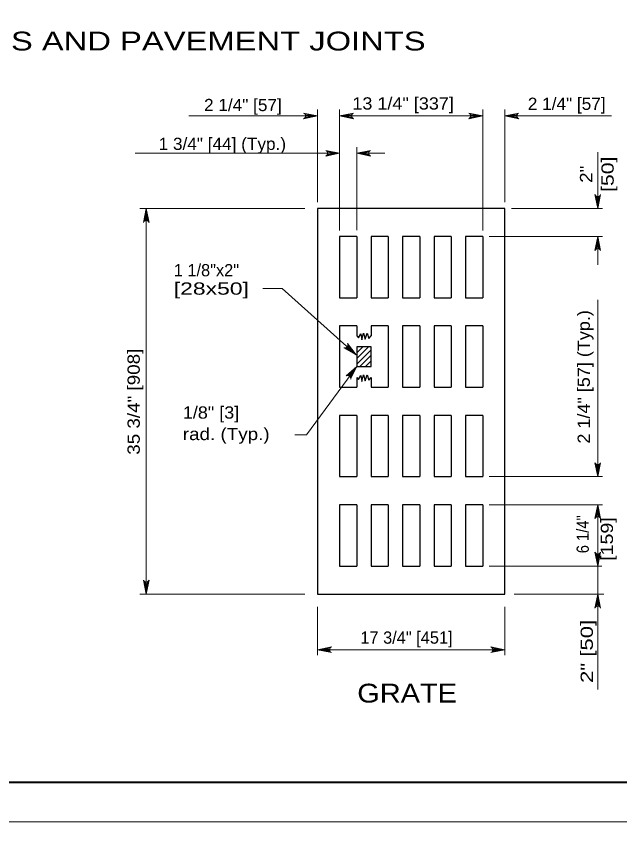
# Model space of a CAD drawing. Extents: x 1083.1 to 1117.1, y 719.4 to 763.4.
# Drawn here: x 1095.88 to 1103.56, y 741.1 to 751.62 of the extents above; entities that cross this region are included whole.
import ezdxf
from ezdxf.enums import TextEntityAlignment as Align

# ---------------------------------------------------------------- set-up
doc = ezdxf.new("R2010")
doc.units = 0
doc.header["$LTSCALE"] = 0.062
doc.linetypes.add('LONG_DASHED', pattern=[7.5, 6, -1.5])
doc.layers.add('1', color=7, linetype='Continuous', lineweight=13)

msp = doc.modelspace()

# ---------------------------------------------------------------- linework, layer by layer
at = {"layer": '1'}
for p, q in [((1099.55183, 750.37458), (1099.71208, 750.35217)), ((1099.55725, 750.3635), (1099.71208, 750.35217)), ((1099.99325, 748.89175), (1099.99325, 750.43542)), ((1100.15358, 750.37458), (1099.99325, 750.35217)), ((1100.14817, 750.3635), (1099.99325, 750.35217)), ((1101.65758, 750.37458), (1101.81792, 750.35217)), ((1101.66308, 750.3635), (1101.81792, 750.35217)), ((1101.81792, 748.89175), (1101.81792, 750.43542)), ((1102.09908, 749.25492), (1102.09908, 750.43542)), ((1102.25942, 750.37458), (1102.09908, 750.35217)), ((1102.254, 750.3635), (1102.09908, 750.35217)), ((1099.71208, 750.35217), (1098.07217, 750.35217)), ((1099.4615, 750.35217), (1099.71208, 750.35217)), ((1099.54992, 750.32733), (1099.71208, 750.35217)), ((1099.55608, 750.33775), (1099.71208, 750.35217)), ((1099.55892, 750.35217), (1099.71208, 750.35217)), ((1100.1465, 750.35217), (1099.99325, 750.35217)), ((1100.14933, 750.33775), (1099.99325, 750.35217)), ((1100.1555, 750.32733), (1099.99325, 750.35217)), ((1101.81792, 750.35217), (1099.99325, 750.35217)), ((1101.65575, 750.32733), (1101.81792, 750.35217)), ((1101.66183, 750.33775), (1101.81792, 750.35217)), ((1101.66467, 750.35217), (1101.81792, 750.35217)), ((1102.25233, 750.35217), (1102.09908, 750.35217)), ((1102.25517, 750.33775), (1102.09908, 750.35217)), ((1102.26125, 750.32733), (1102.09908, 750.35217)), ((1103.45875, 750.35217), (1102.09908, 750.35217)), ((1100.212, 748.89692), (1100.212, 749.95383)), ((1097.3885, 749.87617), (1099.99317, 749.87617)), ((1099.831, 749.85133), (1099.99317, 749.87617)), ((1099.83283, 749.89858), (1099.99317, 749.87617)), ((1099.83708, 749.86175), (1099.99317, 749.87617)), ((1099.83833, 749.8875), (1099.99317, 749.87617)), ((1099.83992, 749.87617), (1099.99317, 749.87617)), ((1100.37233, 749.89858), (1100.212, 749.87617)), ((1100.36692, 749.8875), (1100.212, 749.87617)), ((1100.36525, 749.87617), (1100.212, 749.87617)), ((1100.36808, 749.86175), (1100.212, 749.87617)), ((1100.37425, 749.85133), (1100.212, 749.87617)), ((1100.56867, 749.87617), (1100.212, 749.87617)), ((1103.28267, 749.89067), (1103.28267, 749.17167)), ((1103.26025, 749.33192), (1103.28267, 749.17167)), ((1103.27133, 749.3265), (1103.28267, 749.17167)), ((1103.3075, 749.33383), (1103.28267, 749.17167)), ((1103.29708, 749.32767), (1103.28267, 749.17167)), ((1103.28267, 749.32483), (1103.28267, 749.17167)), ((1099.55058, 749.17167), (1097.44575, 749.17167)), ((1097.50483, 749.00942), (1097.52967, 749.17167)), ((1097.51525, 749.01558), (1097.52967, 749.17167)), ((1097.52967, 749.01842), (1097.52967, 749.17167)), ((1097.541, 749.01675), (1097.52967, 749.17167)), ((1097.55208, 749.01133), (1097.52967, 749.17167)), ((1097.52967, 749.17167), (1097.52967, 744.25725)), ((1102.18242, 749.17167), (1103.34483, 749.17167)), ((1101.90125, 748.81358), (1103.34483, 748.81358)), ((1103.25792, 748.65142), (1103.28267, 748.81358)), ((1103.26825, 748.6575), (1103.28267, 748.81358)), ((1103.28267, 748.81358), (1103.28267, 748.45558)), ((1103.28267, 748.66033), (1103.28267, 748.81358)), ((1103.294, 748.65875), (1103.28267, 748.81358)), ((1103.30508, 748.65325), (1103.28267, 748.81358)), ((1099.25958, 748.15033), (1099.015, 748.15033)), ((1100.2025, 747.30517), (1099.25958, 748.15033)), ((1103.28267, 748.00592), (1103.28267, 745.75417)), ((1100.09658, 747.42075), (1100.2025, 747.30517)), ((1100.099, 747.43258), (1100.2025, 747.30517)), ((1100.06875, 747.39633), (1100.2025, 747.30517)), ((1100.08025, 747.40092), (1100.2025, 747.30517)), ((1100.08908, 747.40817), (1100.2025, 747.30517)), ((1100.212, 747.402), (1100.219, 747.409)), ((1100.212, 747.33125), (1100.28975, 747.409)), ((1100.212, 747.2605), (1100.3605, 747.409)), ((1100.212, 747.18983), (1100.39475, 747.37258)), ((1100.25192, 747.159), (1100.39475, 747.30183)), ((1100.32258, 747.159), (1100.39475, 747.23117)), ((1100.212, 747.159), (1099.57208, 746.28625)), ((1100.09508, 747.04392), (1100.212, 747.159)), ((1100.10708, 747.04258), (1100.212, 747.159)), ((1100.12033, 747.03625), (1100.212, 747.159)), ((1100.12842, 747.02817), (1100.212, 747.159)), ((1100.13408, 747.01717), (1100.212, 747.159)), ((1100.39333, 747.159), (1100.39475, 747.16042)), ((1099.57208, 746.28625), (1099.42258, 746.28625)), ((1103.26025, 745.9145), (1103.28267, 745.75417)), ((1103.27133, 745.909), (1103.28267, 745.75417)), ((1103.3075, 745.91633), (1103.28267, 745.75417)), ((1103.29708, 745.91025), (1103.28267, 745.75417)), ((1103.28267, 745.90742), (1103.28267, 745.75417)), ((1101.90125, 745.75425), (1103.34483, 745.75425)), ((1101.90125, 745.39625), (1103.34483, 745.39625)), ((1103.25792, 745.23392), (1103.28267, 745.39608)), ((1103.26825, 745.24008), (1103.28267, 745.39608)), ((1103.28267, 745.39608), (1103.28267, 744.83275)), ((1103.28267, 745.24292), (1103.28267, 745.39608)), ((1103.294, 745.24125), (1103.28267, 745.39608)), ((1103.30508, 745.23583), (1103.28267, 745.39608)), ((1103.28267, 744.61525), (1103.28267, 744.83275)), ((1103.26025, 744.77558), (1103.28267, 744.61525)), ((1103.27133, 744.77008), (1103.28267, 744.61525)), ((1103.3075, 744.77742), (1103.28267, 744.61525)), ((1103.29708, 744.77133), (1103.28267, 744.61525)), ((1103.28267, 744.7685), (1103.28267, 744.61525)), ((1101.90125, 744.61525), (1103.3345, 744.61525)), ((1103.28267, 744.61525), (1103.28267, 744.25725)), ((1097.50725, 744.4175), (1097.52967, 744.25725)), ((1097.51833, 744.41208), (1097.52967, 744.25725)), ((1097.55442, 744.41942), (1097.52967, 744.25725)), ((1097.54408, 744.41325), (1097.52967, 744.25725)), ((1097.52967, 744.41042), (1097.52967, 744.25725)), ((1099.55058, 744.25725), (1097.44575, 744.25725)), ((1102.2175, 744.25725), (1103.36083, 744.25725)), ((1103.0275, 744.25725), (1103.16408, 744.25725)), ((1103.25792, 744.095), (1103.28267, 744.25725)), ((1103.26825, 744.10117), (1103.28267, 744.25725)), ((1103.28267, 743.04133), (1103.28267, 744.25725)), ((1103.28267, 744.104), (1103.28267, 744.25725)), ((1103.294, 744.10233), (1103.28267, 744.25725)), ((1103.30508, 744.09692), (1103.28267, 744.25725)), ((1099.71208, 744.09575), (1099.71208, 743.4785)), ((1102.09908, 744.09575), (1102.09908, 743.4785)), ((1099.87242, 743.57133), (1099.71208, 743.54892)), ((1099.867, 743.56025), (1099.71208, 743.54892)), ((1099.86533, 743.54892), (1099.71208, 743.54892)), ((1099.86817, 743.5345), (1099.71208, 743.54892)), ((1099.87433, 743.52408), (1099.71208, 743.54892)), ((1099.71208, 743.54892), (1102.09908, 743.54892)), ((1101.93692, 743.52408), (1102.09908, 743.54892)), ((1101.93875, 743.57133), (1102.09908, 743.54892)), ((1101.943, 743.5345), (1102.09908, 743.54892)), ((1101.94417, 743.56025), (1102.09908, 743.54892)), ((1101.94583, 743.54892), (1102.09908, 743.54892))]:
    msp.add_line(p, q, dxfattribs=at)
at = {"layer": '1', "lineweight": 25}
for p, q in [((1100.212, 748.81358), (1100.212, 748.0325)), ((1100.6135, 748.81358), (1100.6135, 748.0325)), ((1101.015, 748.81358), (1101.015, 748.0325)), ((1101.41642, 748.81358), (1101.41642, 748.0325)), ((1101.81792, 748.81358), (1101.81792, 748.0325)), ((1099.99325, 748.0325), (1100.212, 748.0325)), ((1100.39475, 748.0325), (1100.6135, 748.0325)), ((1100.79625, 748.0325), (1101.015, 748.0325)), ((1101.19775, 748.0325), (1101.41642, 748.0325)), ((1101.59917, 748.0325), (1101.81792, 748.0325)), ((1100.212, 747.6745), (1100.212, 747.54958)), ((1100.6135, 747.6745), (1100.39475, 747.6745)), ((1100.39475, 747.6745), (1100.39475, 747.54958)), ((1100.6135, 747.6745), (1100.6135, 747.61242)), ((1100.6135, 747.6745), (1100.6135, 747.54958)), ((1101.015, 747.6745), (1100.79625, 747.6745)), ((1100.79625, 747.6745), (1100.79625, 747.59908)), ((1100.79625, 747.6745), (1100.79625, 747.54958)), ((1101.015, 747.6745), (1101.015, 747.622)), ((1101.015, 747.6745), (1101.015, 747.61242)), ((1101.015, 747.6745), (1101.015, 747.54958)), ((1101.41642, 747.6745), (1101.19775, 747.6745)), ((1101.19775, 747.6745), (1101.19775, 747.5975)), ((1101.19775, 747.6745), (1101.19775, 747.59908)), ((1101.19775, 747.6745), (1101.19775, 747.54958)), ((1101.41642, 747.6745), (1101.41642, 747.62258)), ((1101.41642, 747.6745), (1101.41642, 747.622)), ((1101.41642, 747.6745), (1101.41642, 747.61242)), ((1101.41642, 747.6745), (1101.41642, 747.54958)), ((1101.81792, 747.6745), (1101.59917, 747.6745)), ((1101.59917, 747.6745), (1101.59917, 747.60125)), ((1101.59917, 747.6745), (1101.59917, 747.5975)), ((1101.59917, 747.6745), (1101.59917, 747.59908)), ((1101.59917, 747.6745), (1101.59917, 747.54958)), ((1101.81792, 747.6745), (1101.81792, 746.89342)), ((1102.09908, 744.25725), (1102.09908, 747.68)), ((1100.6135, 747.54958), (1100.6135, 746.89342)), ((1100.79625, 747.54958), (1100.79625, 746.89342)), ((1101.015, 747.54958), (1101.015, 746.89342)), ((1101.19775, 747.54958), (1101.19775, 746.89342)), ((1101.41642, 747.54958), (1101.41642, 746.89342)), ((1101.59917, 747.54958), (1101.59917, 746.89342)), ((1100.212, 747.01842), (1100.212, 746.89342)), ((1100.39475, 747.01842), (1100.39475, 746.89342)), ((1100.39475, 746.89342), (1100.6135, 746.89342)), ((1100.6135, 746.93475), (1100.6135, 746.89342)), ((1100.79625, 746.95317), (1100.79625, 746.89342)), ((1100.79625, 746.89342), (1101.015, 746.89342)), ((1101.015, 746.93475), (1101.015, 746.89342)), ((1101.015, 746.92683), (1101.015, 746.89342)), ((1101.19775, 746.95317), (1101.19775, 746.89342)), ((1101.19775, 746.94525), (1101.19775, 746.89342)), ((1101.19775, 746.89342), (1101.41642, 746.89342)), ((1101.41642, 746.9505), (1101.41642, 746.89342)), ((1101.41642, 746.93475), (1101.41642, 746.89342)), ((1101.41642, 746.92683), (1101.41642, 746.89342)), ((1101.59917, 746.95317), (1101.59917, 746.89342)), ((1101.59917, 746.94525), (1101.59917, 746.89342)), ((1101.59917, 746.94525), (1101.59917, 746.89342)), ((1101.59917, 746.89342), (1101.81792, 746.89342)), ((1100.212, 746.53533), (1100.212, 745.75425)), ((1100.6135, 746.53533), (1100.39475, 746.53533)), ((1100.6135, 746.53533), (1100.6135, 745.75425)), ((1100.79625, 746.53533), (1100.79625, 745.75425)), ((1101.015, 746.53533), (1100.79625, 746.53533)), ((1101.015, 746.53533), (1101.015, 745.75425)), ((1101.19775, 746.53533), (1101.19775, 745.75425)), ((1101.41642, 746.53533), (1101.19775, 746.53533)), ((1101.41642, 746.53533), (1101.41642, 745.75425)), ((1101.59917, 746.53533), (1101.59917, 745.75425)), ((1101.81792, 746.53533), (1101.59917, 746.53533)), ((1101.81792, 746.53533), (1101.81792, 745.75425)), ((1099.99325, 745.75425), (1100.212, 745.75425)), ((1100.79625, 745.75425), (1101.015, 745.75425)), ((1101.19775, 745.75425), (1101.41642, 745.75425)), ((1101.59917, 745.75425), (1101.81792, 745.75425)), ((1100.212, 745.39625), (1100.212, 744.61517)), ((1100.6135, 745.39625), (1100.6135, 744.61517)), ((1101.015, 745.39625), (1101.015, 744.61517)), ((1101.41642, 745.39625), (1101.41642, 744.61517)), ((1101.81792, 745.39625), (1101.81792, 744.61517)), ((1099.99325, 744.61517), (1100.212, 744.61517)), ((1100.39475, 744.61517), (1100.6135, 744.61517)), ((1100.79625, 744.61517), (1101.015, 744.61517)), ((1101.19775, 744.61517), (1101.41642, 744.61517)), ((1101.59917, 744.61517), (1101.81792, 744.61517))]:
    msp.add_line(p, q, dxfattribs=at)
at = {"layer": '1', "linetype": 'LONG_DASHED'}
for points in [[(1083.12642, 741.35408), (1117.12642, 741.35408), (1117.12642, 763.35408), (1083.12642, 763.35408)], [(1083.12642, 719.35408), (1117.12642, 719.35408), (1117.12642, 741.35408), (1083.12642, 741.35408)]]:
    msp.add_lwpolyline(points, close=True, dxfattribs=at)
at = {"layer": '1', "lineweight": 25}
for points in [[(1116.62642, 741.85408), (1085.12642, 741.85408), (1085.12642, 762.85408)], [(1102.09908, 749.17167), (1099.71208, 749.17167), (1099.71208, 744.25725), (1102.09908, 744.25725)], [(1102.09908, 747.68), (1102.09908, 747.71792), (1102.09908, 749.17167)], [(1100.212, 748.81358), (1099.99325, 748.81358), (1099.99325, 748.0325)], [(1100.6135, 748.81358), (1100.39475, 748.81358), (1100.39475, 748.0325)], [(1101.015, 748.81358), (1100.79625, 748.81358), (1100.79625, 748.0325)], [(1101.41642, 748.81358), (1101.19775, 748.81358), (1101.19775, 748.0325)], [(1101.81792, 748.81358), (1101.59917, 748.81358), (1101.59917, 748.0325)], [(1100.212, 747.6745), (1099.99325, 747.6745), (1099.99325, 746.89342), (1100.212, 746.89342)], [(1100.212, 747.54958), (1100.23317, 747.52342), (1100.262, 747.57592), (1100.27775, 747.49717), (1100.29875, 747.58383), (1100.31975, 747.50508), (1100.34342, 747.58383), (1100.36442, 747.51558), (1100.39475, 747.54958)], [(1100.212, 747.01842), (1100.23317, 746.99225), (1100.262, 747.04475), (1100.27775, 746.966), (1100.29875, 747.05267), (1100.31975, 746.97392), (1100.34342, 747.05267), (1100.36442, 746.98442), (1100.39475, 747.01842)], [(1100.212, 746.53533), (1099.99325, 746.53533), (1099.99325, 745.75425)], [(1100.39475, 746.53533), (1100.39475, 745.75425), (1100.6135, 745.75425)], [(1100.212, 745.39625), (1099.99325, 745.39625), (1099.99325, 744.61517)], [(1100.6135, 745.39625), (1100.39475, 745.39625), (1100.39475, 744.61517)], [(1101.015, 745.39625), (1100.79625, 745.39625), (1100.79625, 744.61517)], [(1101.41642, 745.39625), (1101.19775, 745.39625), (1101.19775, 744.61517)], [(1101.81792, 745.39625), (1101.59917, 745.39625), (1101.59917, 744.61517)]]:
    msp.add_lwpolyline(points, dxfattribs=at)
at = {"layer": '1', "lineweight": 40}
msp.add_lwpolyline([(1085.12642, 762.85408), (1116.62642, 762.85408), (1116.62642, 741.85408), (1085.12642, 741.85408)], close=True, dxfattribs=at)
msp.add_lwpolyline([(1085.12642, 762.85408), (1116.62642, 762.85408), (1116.62642, 741.85408), (1085.12642, 741.85408)], close=True, dxfattribs=at)
at = {"layer": '1'}
for points in [[(1099.535, 750.31675), (1099.71208, 750.35217), (1099.535, 750.38758)], [(1099.71208, 749.25492), (1099.71208, 749.64642), (1099.71208, 750.43542)], [(1100.17033, 750.31675), (1099.99325, 750.35217), (1100.17033, 750.38758)], [(1101.64083, 750.31675), (1101.81792, 750.35217), (1101.64083, 750.38758)], [(1102.27617, 750.31675), (1102.09908, 750.35217), (1102.27617, 750.38758)], [(1099.81608, 749.84075), (1099.99317, 749.87617), (1099.81608, 749.91158)], [(1100.38908, 749.84075), (1100.212, 749.87617), (1100.38908, 749.91158)], [(1103.31808, 749.34867), (1103.28267, 749.17167), (1103.24725, 749.34867)], [(1097.49425, 748.99458), (1097.52967, 749.17167), (1097.56508, 748.99458)], [(1103.24725, 748.6365), (1103.28267, 748.81358), (1103.31808, 748.6365)], [(1100.09517, 747.45042), (1100.2025, 747.30517), (1100.0475, 747.39792)], [(1100.07767, 747.03833), (1100.212, 747.159), (1100.13442, 746.99592)], [(1103.31808, 745.93125), (1103.28267, 745.75417), (1103.24725, 745.93125)], [(1103.24725, 745.21908), (1103.28267, 745.39608), (1103.31808, 745.21908)], [(1103.31808, 744.79233), (1103.28267, 744.61525), (1103.24725, 744.79233)], [(1097.56508, 744.43425), (1097.52967, 744.25725), (1097.49425, 744.43425)], [(1103.24725, 744.08017), (1103.28267, 744.25725), (1103.31808, 744.08017)], [(1099.88917, 743.5135), (1099.71208, 743.54892), (1099.88917, 743.58433)], [(1101.922, 743.5135), (1102.09908, 743.54892), (1101.922, 743.58433)]]:
    msp.add_lwpolyline(points, dxfattribs=at)
at = {"layer": '1', "lineweight": 25}
msp.add_lwpolyline([(1100.212, 747.159), (1100.39475, 747.159), (1100.39475, 747.409), (1100.212, 747.409)], close=True, dxfattribs=at)
at = {"layer": '1'}
for centre, start, end in [((1099.52074, 750.35217), 292.08605, 67.91218), ((1100.18464, 750.35217), 112.08782, 247.91395), ((1101.62656, 750.35217), 292.08605, 67.91218), ((1102.29046, 750.35217), 112.08782, 247.91395), ((1099.80181, 749.87617), 292.08605, 67.91218), ((1100.40338, 749.87617), 112.08782, 247.91395), ((1103.28264, 749.36301), 202.08782, 337.91395), ((1097.52969, 748.98026), 22.08782, 157.91395), ((1103.28272, 748.62223), 22.08782, 157.91395), ((1100.06075, 747.43378), 249.85926, 25.68539), ((1100.09756, 747.00564), 345.34924, 121.17536), ((1103.28264, 745.94553), 202.08782, 337.91395), ((1103.28272, 745.20475), 22.08782, 157.91395), ((1103.28264, 744.80662), 202.08782, 337.91395), ((1097.52961, 744.44859), 202.08782, 337.91395), ((1103.28272, 744.06584), 22.08782, 157.91395), ((1099.90349, 743.54895), 112.08782, 247.91395), ((1101.90771, 743.54895), 292.08605, 67.91218)]:
    msp.add_arc(centre, 0.03822, start, end, dxfattribs=at)

# ---------------------------------------------------------------- texts
for s, height, width, p in [('PLAN OF CATCH BASINS AND PAVEMENT JOINTS', 0.24, 1.3, (1091.09858, 751.18608)), ('13 1/4" [337]', 0.156, 1.1, (1100.15617, 750.43317)), ('[28x50]', 0.156, 1.4, (1097.87975, 748.07367)), ('1/8" [3]', 0.156, 1.1, (1097.99525, 746.49375)), ('rad. (Typ.)', 0.156, 1.15, (1097.99525, 746.21967)), ('GRATE', 0.24, 1.15, (1100.2185, 742.87492))]:
    msp.add_text(s, height=height, dxfattribs=dict(at, width=width)).set_placement(p)
at = {"layer": '1', "width": 1.05}
for s, p in [('2 1/4" [57]', (1098.76121, 750.41333)), ('2 1/4" [57]', (1102.88779, 750.429)), ('1 3/4" [44] (Typ.)', (1098.49921, 749.9185))]:
    msp.add_text(s, height=0.156, dxfattribs=at).set_placement(p, align=Align.CENTER)
at = {"layer": '1'}
for s, width, p in [('[50]', 1.3, (1103.48658, 749.60854)), ('2"', 1.15, (1103.2125, 749.60854)), ('2 1/4" [57] (Typ.)', 1.1, (1103.18267, 747.02608)), ('6 1/4"', 0.9, (1103.1695, 745.02004)), ('[159]', 1.2, (1103.47758, 744.95896))]:
    msp.add_text(s, height=0.156, rotation=90, dxfattribs=dict(at, width=width)).set_placement(p, align=Align.CENTER)
for s, p in [('1 1/8"x2"', (1097.87975, 748.30767)), ('17 3/4" [451]', (1100.25775, 743.62525))]:
    msp.add_text(s, height=0.156, dxfattribs=at).set_placement(p)
for s, width, p in [('35 3/4" [908]', 1.15, (1097.4465, 746.03333)), ('2" [50]', 1.35, (1103.2215, 743.12467))]:
    msp.add_text(s, height=0.156, rotation=90, dxfattribs=dict(at, width=width)).set_placement(p)

doc.saveas('drawing.dxf')
